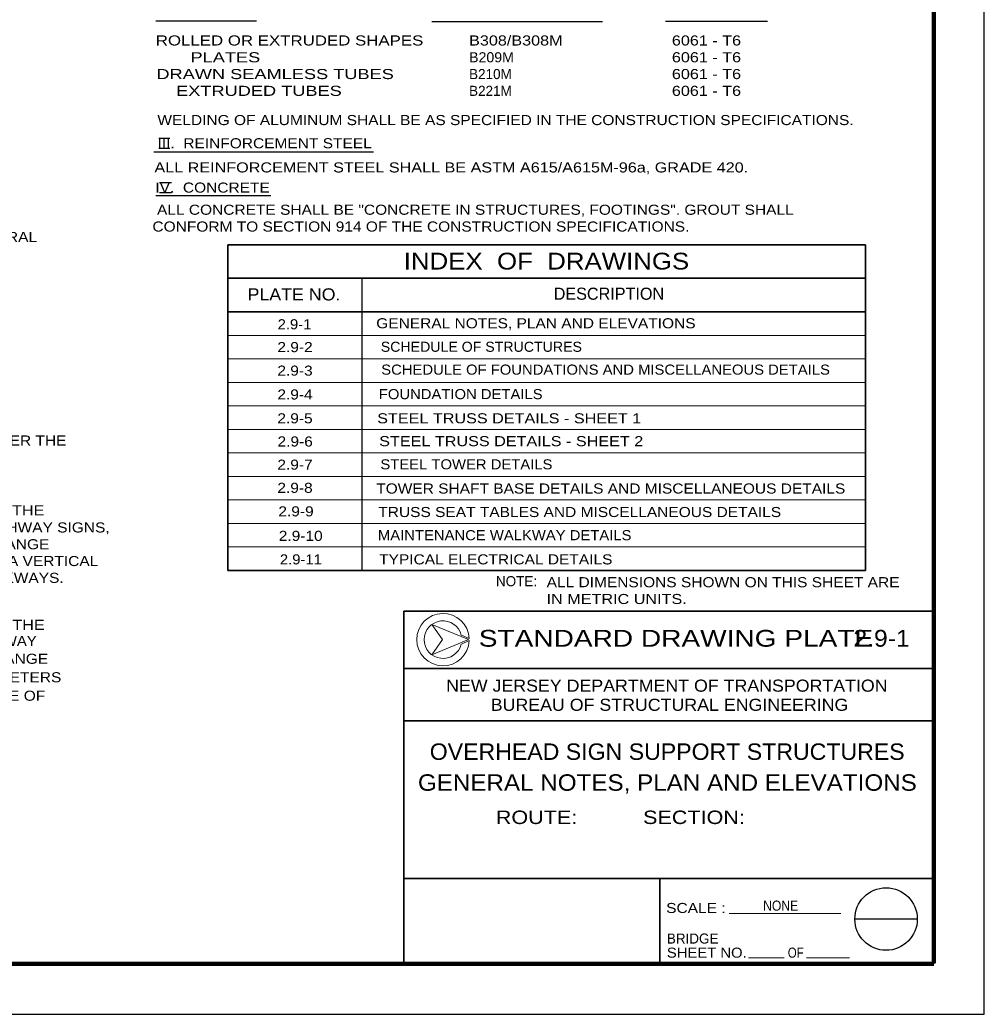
# Model space of a CAD drawing. Extents: x 312601.858 to 312602.699, y 144420.109 to 144420.704.
# Drawn here: x 312602.4116 to 312602.6988, y 144420.1095 to 144420.4055 of the extents above; entities that cross this region are included whole.
import ezdxf
from ezdxf.enums import TextEntityAlignment as Align

# ---------------------------------------------------------------- set-up
doc = ezdxf.new("R2010")
doc.units = 0
doc.header["$LTSCALE"] = 0.0012
for name, color, linetype, lineweight in [('1', 7, 'Continuous', 25), ('2', 7, 'Continuous', 13), ('39', 7, 'Continuous', 13)]:
    doc.layers.add(name, color=color, linetype=linetype, lineweight=lineweight)
doc.layers.add('4', color=7, linetype='Continuous')

msp = doc.modelspace()

# ---------------------------------------------------------------- linework, layer by layer
at = {"layer": '1', "lineweight": 35}
for p, q in [((312602.4735, 144420.3386), (312602.4735, 144420.2416)), ((312602.6635, 144420.3386), (312602.4735, 144420.3386)), ((312602.6635, 144420.3386), (312602.6635, 144420.2416)), ((312602.6635, 144420.3286), (312602.4735, 144420.3286)), ((312602.6635, 144420.3186), (312602.4735, 144420.3186)), ((312602.6635, 144420.2416), (312602.4735, 144420.2416))]:
    msp.add_line(p, q, dxfattribs=at)
at = {"layer": '1'}
msp.add_line((312602.5135, 144420.3286), (312602.5135, 144420.2416), dxfattribs=at)
at = {"layer": '1', "lineweight": 13}
for p, q in [((312602.6635, 144420.3116), (312602.4735, 144420.3116)), ((312602.6635, 144420.3046), (312602.4735, 144420.3046)), ((312602.6635, 144420.2976), (312602.4735, 144420.2976)), ((312602.6635, 144420.2906), (312602.4735, 144420.2906)), ((312602.6635, 144420.2836), (312602.4735, 144420.2836)), ((312602.6635, 144420.2766), (312602.4735, 144420.2766)), ((312602.6635, 144420.2696), (312602.4735, 144420.2696)), ((312602.6635, 144420.2626), (312602.4735, 144420.2626)), ((312602.6635, 144420.2556), (312602.4735, 144420.2556)), ((312602.6635, 144420.2486), (312602.4735, 144420.2486)), ((312602.5431, 144420.2197), (312602.5454, 144420.2207)), ((312602.6286, 144420.1263), (312602.6392, 144420.1263)), ((312602.6459, 144420.1263), (312602.6587, 144420.1263))]:
    msp.add_line(p, q, dxfattribs=at)
for points in [[(312602.5452, 144420.221), (312602.5343, 144420.2255), (312602.5452, 144420.221)], [(312602.5454, 144420.2213), (312602.5431, 144420.2223), (312602.543, 144420.2223)]]:
    msp.add_lwpolyline(points, dxfattribs=at)
for points in [[(312602.5452, 144420.221), (312602.5343, 144420.2255), (312602.5375, 144420.221), (312602.5343, 144420.2165)], [(312602.5375, 144420.221), (312602.5343, 144420.2165), (312602.5452, 144420.221), (312602.5343, 144420.2255)]]:
    msp.add_lwpolyline(points, close=True, dxfattribs=at)
for radius, start, end in [(0.0078026, 2.21392, 357.78608), (0.0056, 13.69411, 346.30589)]:
    msp.add_arc((312602.5376, 144420.221), radius, start, end, dxfattribs=at)
at = {"layer": '2', "lineweight": 25}
for p, q in [((312602.4521, 144420.4052), (312602.4821, 144420.4052)), ((312602.5343, 144420.405), (312602.5851, 144420.405)), ((312602.6039, 144420.4051), (312602.6343, 144420.4051)), ((312602.453, 144420.3703), (312602.4563, 144420.3703)), ((312602.453, 144420.3673), (312602.4563, 144420.3673)), ((312602.4515, 144420.3662), (312602.5169, 144420.3662)), ((312602.4532, 144420.3571), (312602.4568, 144420.3571)), ((312602.4521, 144420.3532), (312602.4863, 144420.3532)), ((312602.4532, 144420.3541), (312602.4568, 144420.3541))]:
    msp.add_line(p, q, dxfattribs=at)
at = {"layer": '39', "lineweight": 25}
for p, q in [((312602.6988, 144420.1095), (312602.6988, 144420.7035)), ((312602.6789, 144420.1378), (312602.6603, 144420.1378)), ((312601.8578, 144420.1095), (312602.6988, 144420.1095))]:
    msp.add_line(p, q, dxfattribs=at)
at = {"layer": '39', "lineweight": 158}
for p, q in [((312602.6838, 144420.1247), (312602.6838, 144420.6645)), ((312601.9088, 144420.1245), (312602.6838, 144420.1245))]:
    msp.add_line(p, q, dxfattribs=at)
at = {"layer": '39', "lineweight": 35}
for p, q in [((312602.526, 144420.1245), (312602.526, 144420.2295)), ((312602.526, 144420.2124), (312602.6838, 144420.2124)), ((312602.526, 144420.1968), (312602.6838, 144420.1968)), ((312602.526, 144420.1499), (312602.6838, 144420.1499)), ((312602.6022, 144420.1248), (312602.6022, 144420.1499)), ((312602.6022, 144420.1248), (312602.6022, 144420.1499))]:
    msp.add_line(p, q, dxfattribs=at)
at = {"layer": '39'}
for p, q in [((312602.6022, 144420.1499), (312602.6838, 144420.1499)), ((312602.6229, 144420.1395), (312602.6561, 144420.1395))]:
    msp.add_line(p, q, dxfattribs=at)
at = {"layer": '39', "lineweight": 35}
msp.add_lwpolyline([(312602.526, 144420.2295), (312602.6838, 144420.2295), (312602.6838, 144420.1245)], dxfattribs=at)
at = {"layer": '39'}
msp.add_lwpolyline([(312602.5452, 144420.221), (312602.5343, 144420.2255), (312602.5375, 144420.221), (312602.5343, 144420.2165)], close=True, dxfattribs=at)
at = {"layer": '39', "lineweight": 25}
msp.add_circle((312602.6696, 144420.1378), 0.0093005, dxfattribs=at)

# ---------------------------------------------------------------- texts
at = {"layer": '1'}
for s, width, p in [('B308/B308M', 1.2, (312602.5454, 144420.3979)), ('6061 - T6', 1.2, (312602.6058, 144420.3979)), ('B209M', 1.05, (312602.5454, 144420.3929)), ('6061 - T6', 1.2, (312602.6058, 144420.3929)), ('6061 - T6', 1.2, (312602.6058, 144420.3879)), ('6061 - T6', 1.2, (312602.6058, 144420.3829))]:
    msp.add_text(s, height=0.003, dxfattribs=dict(at, width=width)).set_placement(p)
for s, p in [('B210M', (312602.5454, 144420.3879)), ('B221M', (312602.5454, 144420.3829))]:
    msp.add_text(s, height=0.003, dxfattribs=at).set_placement(p)
at = {"layer": '2'}
for s, height, width, p in [('ROLLED OR EXTRUDED SHAPES       ', 0.003, 1.25, (312602.4968, 144420.3979)), ('PLATES                   ', 0.003, 1.35, (312602.4871, 144420.3929)), ('DRAWN SEAMLESS TUBES           ', 0.003, 1.35, (312602.4959, 144420.3879)), ('EXTRUDED TUBES                 ', 0.003, 1.35, (312602.4956, 144420.3829)), ('WELDING OF ALUMINUM SHALL BE AS SPECIFIED IN THE CONSTRUCTION SPECIFICATIONS.', 0.003, 1.15, (312602.55625, 144420.3742)), ('III.  REINFORCEMENT STEEL', 0.003, 1.15, (312602.4845, 144420.3673)), ('ALL REINFORCEMENT STEEL SHALL BE ASTM A615/A615M-96a, GRADE 420.', 0.003, 1.2, (312602.5401, 144420.3601)), ('IV.  CONCRETE', 0.003, 1.15, (312602.469, 144420.3541)), ('ALL CONCRETE SHALL BE "CONCRETE IN STRUCTURES, FOOTINGS". GROUT SHALL ', 0.003, 1.15, (312602.5479, 144420.3475)), ('CONFORM TO SECTION 914 OF THE CONSTRUCTION SPECIFICATIONS.', 0.003, 1.15, (312602.53105, 144420.3425)), ('AND STRUCTURES, AND 1994 AASHTO STANDARD SPECIFICATIONS FOR STRUCTURAL', 0.003, 1.15, (312602.31855, 144420.3394)), ('INDEX  OF  DRAWINGS', 0.005, 1.15, (312602.56845, 144420.3312)), ('PLATE NO.', 0.0036, 1.1, (312602.49325, 144420.322)), ('2.9-1', 0.003, 1.1, (312602.4934, 144420.3134)), ('GENERAL NOTES, PLAN AND ELEVATIONS', 0.003, 1.15, (312602.5653, 144420.3137)), ('2.9-2', 0.003, 1.15, (312602.49355, 144420.3066)), ('SCHEDULE OF STRUCTURES', 0.003, 1.05, (312602.54905, 144420.3067)), ('2.9-3', 0.003, 1.15, (312602.49355, 144420.2996)), ('SCHEDULE OF FOUNDATIONS AND MISCELLANEOUS DETAILS', 0.003, 1.1, (312602.58605, 144420.2999)), ('2.9-4', 0.003, 1.15, (312602.49355, 144420.2925)), ('FOUNDATION DETAILS', 0.003, 1.1, (312602.5429, 144420.2926)), ('2.9-5', 0.003, 1.15, (312602.49355, 144420.2854)), ('STEEL TRUSS DETAILS - SHEET 1', 0.003, 1.2, (312602.55735, 144420.2854)), ('ALL STRUCTURAL DETAILS HAVE BEEN DESIGNED FOR FATIGUE RESISTANCE UNDER THE', 0.003, 1.15, (312602.3228, 144420.2788)), ('2.9-6', 0.003, 1.15, (312602.4936, 144420.2785)), ('STEEL TRUSS DETAILS - SHEET 2', 0.003, 1.2, (312602.55795, 144420.2786)), ('2.9-7', 0.003, 1.15, (312602.49355, 144420.2716)), ('STEEL TOWER DETAILS', 0.003, 1.1, (312602.5446, 144420.2717)), ('2.9-8', 0.003, 1.15, (312602.49355, 144420.2647)), ('TOWER SHAFT BASE DETAILS AND MISCELLANEOUS DETAILS', 0.003, 1.15, (312602.5876, 144420.2645)), ('WHERE Cd IS THE DRAG COEFFICIENT SPECIFIED IN SECTION 1.2.5 OF THE', 0.003, 1.2, (312602.3301, 144420.258)), ('2.9-9', 0.003, 1.15, (312602.49385, 144420.2577)), ('TRUSS SEAT TABLES AND MISCELLANEOUS DETAILS', 0.003, 1.15, (312602.57835, 144420.2575)), ('1994 STANDARD SPECIFICATIONS FOR STRUCTURAL SUPPORTS FOR HIGHWAY SIGNS,', 0.003, 1.15, (312602.3394, 144420.2529)), ('2.9-10', 0.003, 1.15, (312602.49525, 144420.2504)), ('MAINTENANCE WALKWAY DETAILS', 0.003, 1.1, (312602.556, 144420.2506)), ('LUMINAIRES, AND TRAFFIC SIGNALS. NATURAL WIND GUST PRESSURE RANGE', 0.003, 1.15, (312602.33105, 144420.2479)), ('APPLIED IN THE HORIZONTAL DIRECTION TO THE AREA PROJECTED ON A VERTICAL', 0.003, 1.15, (312602.33935, 144420.2429)), ('2.9-11', 0.003, 1.1, (312602.4953, 144420.2434)), ('TYPICAL ELECTRICAL DETAILS', 0.003, 1.15, (312602.55335, 144420.2434)), ('PLANE OF ALL SUPPORT STRUCTURE MEMBERS, SIGN PANELS AND WALKWAYS.', 0.003, 1.15, (312602.33275, 144420.2379)), ('WHERE Cd IS THE DRAG COEFFICIENT SPECIFIED IN SECTION 1.2.5 OF THE', 0.003, 1.2, (312602.3302, 144420.2239)), ('2.9-1', 0.005, 1.1, (312602.66825, 144420.2189)), ('1994 STANDARD SPECIFICATIONS FOR STRUCTURAL SUPPORTS FOR HIGHWAY', 0.003, 1.1, (312602.33005, 144420.2191)), ('SIGNS, LUMINAIRES, AND TRAFFIC SIGNALS.  TRUCK GUST PRESSURE RANGE', 0.003, 1.15, (312602.3312, 144420.2138)), ('APPLIED IN THE UPWARD VERTICAL DIRECTION WITHIN THE MIDDLE 11 METERS', 0.003, 1.15, (312602.33295, 144420.2083)), ('OF THE TRUSS SPAN TO THE AREA PROJECTED ON A HORIZONTAL PLANE OF', 0.003, 1.15, (312602.33085, 144420.2028)), ('OVERHEAD SIGN SUPPORT STRUCTURES', 0.0049, 1.05, (312602.6044, 144420.1852)), ('GENERAL NOTES, PLAN AND ELEVATIONS', 0.0049, 1.1, (312602.60445, 144420.176)), ('NONE', 0.003, 0.9, (312602.6382, 144420.1403))]:
    msp.add_text(s, height=height, dxfattribs=dict(at, width=width)).set_placement(p, align=Align.CENTER)
msp.add_text('DESCRIPTION', height=0.0036, dxfattribs=at).set_placement((312602.58705, 144420.3222), align=Align.CENTER)
at = {"layer": '39'}
for s, height, width, p in [('STANDARD DRAWING PLATE       ', 0.005, 1.25, (312602.61515, 144420.2189)), ('NEW JERSEY DEPARTMENT OF TRANSPORTATION', 0.003599, 1.1, (312602.6043, 144420.2055)), ('BUREAU OF STRUCTURAL ENGINEERING', 0.0036, 1.1, (312602.6051, 144420.1998)), ('ROUTE:           SECTION:', 0.004, 1.2, (312602.59045, 144420.1661)), ('SCALE :', 0.003, 1.15, (312602.61295, 144420.1396)), ('SCALE :', 0.003, 1.15, (312602.61295, 144420.1396)), ('SCALE :', 0.003, 1.15, (312602.61295, 144420.1396)), ('OF', 0.003, 0.85, (312602.6427, 144420.1263))]:
    msp.add_text(s, height=height, dxfattribs=dict(at, width=width)).set_placement(p, align=Align.CENTER)
msp.add_text('BRIDGE', height=0.003, dxfattribs=at).set_placement((312602.6043, 144420.1305))
msp.add_text('BRIDGE', height=0.003, dxfattribs=at).set_placement((312602.6043, 144420.1305))
msp.add_text('BRIDGE', height=0.003, dxfattribs=at).set_placement((312602.6043, 144420.1305))
at = {"layer": '39', "width": 1.1}
msp.add_text('SHEET NO.', height=0.003, dxfattribs=at).set_placement((312602.6043, 144420.1263))
msp.add_text('SHEET NO.', height=0.003, dxfattribs=at).set_placement((312602.6043, 144420.1263))
msp.add_text('SHEET NO.', height=0.003, dxfattribs=at).set_placement((312602.6043, 144420.1263))
at = {"layer": '4'}
msp.add_text('NOTE:', height=0.003, dxfattribs=at).set_placement((312602.5534, 144420.2369))
for s, width, p in [('ALL DIMENSIONS SHOWN ON THIS SHEET ARE', 1.15, (312602.5685, 144420.2366)), ('IN METRIC UNITS.', 1.2, (312602.5685, 144420.2316))]:
    msp.add_text(s, height=0.003, dxfattribs=dict(at, width=width)).set_placement(p)

doc.saveas('drawing.dxf')
